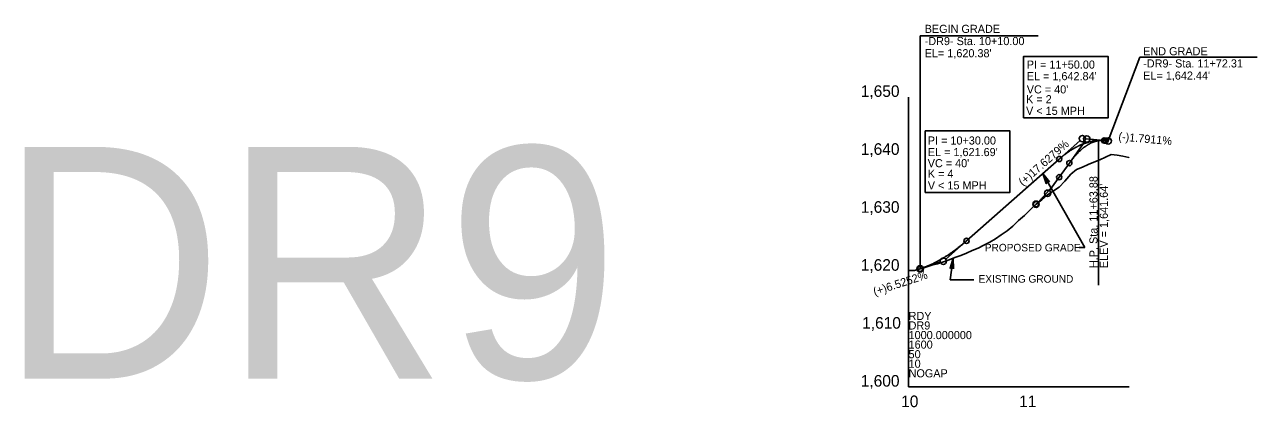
# Model space of a CAD drawing. Extents: x 498575 to 532350, y 405181 to 484585.
# Drawn here: x 526521 to 527585, y 462927 to 463257 of the extents above; entities that cross this region are included whole.
import ezdxf

# ---------------------------------------------------------------- set-up
doc = ezdxf.new("R2010")
doc.units = 0
for name, color, linetype in [('Exist Profile Cell', 7, 'Continuous'), ('Exist Vertical Profile Ground Line', 7, 'Continuous'), ('Exist Vertical Profile Horizontal Axis Label Major', 7, 'Continuous'), ('Exist Vertical Profile Vertical Axis Label', 7, 'Continuous'), ('Prop Grid Mask', 7, 'Continuous'), ('Prop PFL Text', 7, 'Continuous'), ('Prop Vertical Profile Curve Label', 7, 'Continuous'), ('Prop Vertical Profile Grade', 7, 'Continuous'), ('Prop Vertical Profile Grade Label', 7, 'Continuous'), ('Prop Vertical Profile Strip Grade', 7, 'Continuous'), ('Prop VPI Label', 7, 'Continuous'), ('Scratch_Level_5', 7, 'Continuous'), ('Scratch_Level_7', 7, 'Continuous')]:
    doc.layers.add(name, color=color, linetype=linetype)

msp = doc.modelspace()

# ---------------------------------------------------------------- linework, layer by layer
at = {"layer": 'Exist Profile Cell'}
for q in [(527283.8, 463194.6), (527474.1, 462944.6), (527283.8, 462944.6)]:
    msp.add_line((527283.8, 462944.6), q, dxfattribs=at)
at = {"layer": 'Exist Vertical Profile Ground Line'}
msp.add_lwpolyline([(527283.8, 463044.9), (527288.8, 463045), (527293.8, 463046.5), (527298.8, 463048), (527303.8, 463049.5), (527308.8, 463050.9), (527313.8, 463052.4), (527318.8, 463054.3), (527323.8, 463056.1), (527328.8, 463058), (527333.8, 463060), (527338.8, 463062.2), (527343.8, 463064.4), (527348.8, 463066.8), (527353.8, 463069.4), (527358.8, 463072.4), (527363.8, 463075.8), (527368.8, 463079.3), (527373.8, 463083.4), (527378.8, 463088.1), (527383.8, 463092.6), (527388.8, 463097.4), (527393.8, 463102.2), (527398.8, 463105.9), (527403.8, 463110.3), (527408.8, 463113.7), (527413.8, 463116.9), (527418.8, 463122.1), (527423.8, 463128), (527428.8, 463132.2), (527433.8, 463134.3), (527438.8, 463136.6), (527443.8, 463138.5), (527448.8, 463140.6), (527453.8, 463142.7), (527458.8, 463145.1), (527463.8, 463144.6), (527468.8, 463143.6), (527473.8, 463142.4), (527474.1, 463142.3)], dxfattribs=at)
at = {"layer": 'Prop Grid Mask'}
for points in [[(527383, 463176.7), (527456, 463176.7), (527456, 463229.8), (527383, 463229.8)], [(527298.2, 463112.4), (527371.2, 463112.4), (527371.2, 463165.5), (527298.2, 463165.5)]]:
    msp.add_lwpolyline(points, close=True, dxfattribs=at)
at = {"layer": 'Prop PFL Text'}
for p, q in [((527399.6, 463128.6), (527435.8, 463064.9)), ((527431.1, 463064.9), (527435.8, 463064.9)), ((527319.8, 463037), (527322.4, 463055.7)), ((527340.2, 463037), (527319.8, 463037))]:
    msp.add_line(p, q, dxfattribs=at)
for points in [[(527405.3, 463121.5), (527399.6, 463128.6), (527402.6, 463120), (527403.4, 463121.7)], [(527322.7, 463046.5), (527322.4, 463055.7), (527319.6, 463046.9), (527321.3, 463047.8)]]:
    msp.add_lwpolyline(points, close=True, dxfattribs=at)
at = {"layer": 'Prop Vertical Profile Curve Label'}
for centre in [(527453.8, 463157), (527413.8, 463141.2), (527333.8, 463070.6), (527293.8, 463046.5)]:
    msp.add_circle(centre, 2.25, dxfattribs=at)
at = {"layer": 'Prop Vertical Profile Grade'}
for p, q in [((527453.8, 463157), (527456.1, 463156.8)), ((527333.8, 463070.6), (527413.8, 463141.2))]:
    msp.add_line(p, q, dxfattribs=at)
for points in [[(527413.8, 463141.2), (527414.6, 463141.8), (527415.4, 463142.5), (527416.2, 463143.2), (527417, 463143.8), (527417.8, 463144.5), (527418.6, 463145.1), (527419.4, 463145.7), (527420.2, 463146.3), (527421, 463146.9), (527421.8, 463147.4), (527422.6, 463148), (527423.4, 463148.5), (527424.2, 463149), (527425, 463149.5), (527425.8, 463150), (527426.6, 463150.4), (527427.4, 463150.9), (527428.2, 463151.3), (527429, 463151.7), (527429.8, 463152.1), (527430.6, 463152.5), (527431.4, 463152.9), (527432.2, 463153.3), (527433, 463153.6), (527433.8, 463153.9), (527434.6, 463154.2), (527435.4, 463154.5), (527436.2, 463154.8), (527437, 463155.1), (527437.8, 463155.3), (527438.6, 463155.5), (527439.4, 463155.8), (527440.2, 463156), (527441, 463156.1), (527441.8, 463156.3), (527442.6, 463156.5), (527443.4, 463156.6), (527444.2, 463156.7), (527445, 463156.8), (527445.8, 463156.9), (527446.6, 463157), (527447.4, 463157.1), (527448.2, 463157.1), (527449, 463157.1), (527449.8, 463157.2), (527450.6, 463157.1), (527451.4, 463157.1), (527452.2, 463157.1), (527453, 463157.1), (527453.8, 463157)], [(527293.8, 463046.5), (527294.6, 463046.8), (527295.4, 463047), (527296.2, 463047.3), (527297, 463047.6), (527297.8, 463047.9), (527298.6, 463048.2), (527299.4, 463048.5), (527300.2, 463048.9), (527301, 463049.2), (527301.8, 463049.5), (527302.6, 463049.9), (527303.4, 463050.3), (527304.2, 463050.6), (527305, 463051), (527305.8, 463051.4), (527306.6, 463051.8), (527307.4, 463052.2), (527308.2, 463052.6), (527309, 463053), (527309.8, 463053.5), (527310.6, 463053.9), (527311.4, 463054.4), (527312.2, 463054.8), (527313, 463055.3), (527313.8, 463055.8), (527314.6, 463056.3), (527315.4, 463056.8), (527316.2, 463057.3), (527317, 463057.8), (527317.8, 463058.3), (527318.6, 463058.8), (527319.4, 463059.4), (527320.2, 463059.9), (527321, 463060.5), (527321.8, 463061.1), (527322.6, 463061.6), (527323.4, 463062.2), (527324.2, 463062.8), (527325, 463063.4), (527325.8, 463064), (527326.6, 463064.7), (527327.4, 463065.3), (527328.2, 463065.9), (527329, 463066.6), (527329.8, 463067.2), (527330.6, 463067.9), (527331.4, 463068.6), (527332.2, 463069.2), (527333, 463069.9), (527333.8, 463070.6)]]:
    msp.add_spline(points, degree=3, dxfattribs=at)
at = {"layer": 'Prop Vertical Profile Strip Grade'}
msp.add_line((527447.7, 463032.4), (527447.7, 463157.1), dxfattribs=at)
at = {"layer": 'Prop VPI Label'}
for p, q in [((527293.8, 463247.5), (527395.7, 463247.5)), ((527293.8, 463046.5), (527293.8, 463247.5)), ((527456, 463157), (527483.5, 463229)), ((527483.5, 463229), (527584.8, 463229)), ((527413.8, 463141.2), (527431.7, 463157)), ((527453.8, 463157), (527436.5, 463158.5)), ((527333.8, 463070.6), (527315.9, 463054.8)), ((527293.8, 463046.5), (527311.2, 463052.2))]:
    msp.add_line(p, q, dxfattribs=at)
for centre in [(527433.8, 463158.8), (527456.1, 463156.8), (527313.8, 463053), (527293.8, 463046.5)]:
    msp.add_circle(centre, 2.75, dxfattribs=at)
at = {"layer": 'Scratch_Level_5'}
for p, q in [((527422.6, 463137.7), (527435.9, 463156.2)), ((527452.6, 463157.1), (527440.3, 463158.2)), ((527452.6, 463157.1), (527456.1, 463156.8)), ((527413.8, 463125.5), (527422.6, 463137.7)), ((527413.8, 463125.5), (527405.4, 463113.9)), ((527393.8, 463102.2), (527401.8, 463109.8))]:
    msp.add_line(p, q, dxfattribs=at)
for centre, radius in [((527437.6, 463158.5), 2.75), ((527452.6, 463157.1), 2.25), ((527456.1, 463156.8), 2.75), ((527422.6, 463137.7), 2.25), ((527413.8, 463125.5), 2.25), ((527403.8, 463111.7), 2.75), ((527393.8, 463102.2), 2.75), ((527393.8, 463102.2), 2.25)]:
    msp.add_circle(centre, radius, dxfattribs=at)
for points in [[(527422.6, 463137.7), (527423.2, 463138.5), (527423.8, 463139.3), (527424.4, 463140.1), (527425, 463140.9), (527425.6, 463141.6), (527426.2, 463142.3), (527426.8, 463143.1), (527427.4, 463143.8), (527428, 463144.4), (527428.6, 463145.1), (527429.2, 463145.7), (527429.8, 463146.4), (527430.4, 463147), (527431, 463147.6), (527431.6, 463148.1), (527432.2, 463148.7), (527432.8, 463149.2), (527433.4, 463149.8), (527434, 463150.3), (527434.6, 463150.8), (527435.2, 463151.2), (527435.8, 463151.7), (527436.4, 463152.1), (527437, 463152.5), (527437.6, 463152.9), (527438.2, 463153.3), (527438.8, 463153.7), (527439.4, 463154), (527440, 463154.3), (527440.6, 463154.6), (527441.2, 463154.9), (527441.8, 463155.2), (527442.4, 463155.5), (527443, 463155.7), (527443.6, 463155.9), (527444.2, 463156.1), (527444.8, 463156.3), (527445.4, 463156.5), (527446, 463156.6), (527446.6, 463156.8), (527447.2, 463156.9), (527447.8, 463157), (527448.4, 463157), (527449, 463157.1), (527449.6, 463157.1), (527450.2, 463157.2), (527450.8, 463157.2), (527451.4, 463157.2), (527452, 463157.1), (527452.6, 463157.1)], [(527393.8, 463102.2), (527394.2, 463102.6), (527394.6, 463103), (527395, 463103.4), (527395.4, 463103.7), (527395.8, 463104.1), (527396.2, 463104.5), (527396.6, 463104.9), (527397, 463105.3), (527397.4, 463105.8), (527397.8, 463106.2), (527398.2, 463106.6), (527398.6, 463107), (527399, 463107.4), (527399.4, 463107.9), (527399.8, 463108.3), (527400.2, 463108.7), (527400.6, 463109.2), (527401, 463109.6), (527401.4, 463110), (527401.8, 463110.5), (527402.2, 463110.9), (527402.6, 463111.4), (527403, 463111.9), (527403.4, 463112.3), (527403.8, 463112.8), (527404.2, 463113.3), (527404.6, 463113.7), (527405, 463114.2), (527405.4, 463114.7), (527405.8, 463115.2), (527406.2, 463115.6), (527406.6, 463116.1), (527407, 463116.6), (527407.4, 463117.1), (527407.8, 463117.6), (527408.2, 463118.1), (527408.6, 463118.6), (527409, 463119.1), (527409.4, 463119.7), (527409.8, 463120.2), (527410.2, 463120.7), (527410.6, 463121.2), (527411, 463121.8), (527411.4, 463122.3), (527411.8, 463122.8), (527412.2, 463123.4), (527412.6, 463123.9), (527413, 463124.4), (527413.4, 463125), (527413.8, 463125.5)]]:
    msp.add_spline(points, degree=3, dxfattribs=at)

# ---------------------------------------------------------------- texts
at = {"layer": 'Exist Profile Cell'}
for s, p in [('RDY', (527283.8, 463002.3)), ('DR9', (527283.8, 462994.1)), ('1000.000000', (527283.8, 462985.8)), ('1600', (527283.8, 462977.6)), ('50', (527283.8, 462969.3)), ('10', (527283.8, 462961.1)), ('NOGAP', (527283.8, 462952.8))]:
    msp.add_text(s, height=7, dxfattribs=at).set_placement(p)
at = {"layer": 'Exist Vertical Profile Horizontal Axis Label Major'}
for s, p in [('10', (527277.4, 462927.1)), ('11', (527379.2, 462927.1))]:
    msp.add_text(s, height=10, dxfattribs=at).set_placement(p)
at = {"layer": 'Exist Vertical Profile Vertical Axis Label'}
for s, p in [('1,650', (527242.5, 463194.8)), ('1,640', (527242.5, 463144.8)), ('1,630', (527242.5, 463094.8)), ('1,620', (527242.5, 463044.8)), ('1,610', (527243.7, 462994.8)), ('1,600', (527242.5, 462944.8))]:
    msp.add_text(s, height=10, dxfattribs=at).set_placement(p)
at = {"layer": 'Prop PFL Text'}
for s, p in [('PROPOSED GRADE', (527349.6, 463061.5)), ('EXISTING GROUND', (527344.2, 463034.5))]:
    msp.add_text(s, height=6.516, dxfattribs=at).set_placement(p)
at = {"layer": 'Prop Vertical Profile Curve Label'}
for s, p in [("VC = 40'", (527385.8, 463197.8)), ('V < 15 MPH ', (527385.2, 463179.3)), ("VC = 40'", (527300.3, 463134.1)), ('V < 15 MPH ', (527300.4, 463115))]:
    msp.add_text(s, height=7, dxfattribs=at).set_placement(p)
at = {"layer": 'Prop Vertical Profile Grade Label'}
for s, rotation, p in [('(-)1.7911%', 354.8825, (527464.7, 463157.3)), ('(+)17.6279%', 41.3928, (527382.5, 463117.5)), ('(+)6.5252%', 18.0694, (527254.6, 463023.2))]:
    msp.add_text(s, height=7, rotation=rotation, dxfattribs=at).set_placement(p)
at = {"layer": 'Prop Vertical Profile Strip Grade'}
for s, p in [('H.P. Sta. 11+63.88', (527446.9, 463047.1)), ("ELEV = 1,641.64'", (527455.8, 463047.1))]:
    msp.add_text(s, height=7, rotation=90, dxfattribs=at).set_placement(p)
at = {"layer": 'Prop VPI Label'}
for s, p in [('BEGIN GRADE', (527297.7, 463250)), ('-DR9- Sta. 10+10.00', (527297.7, 463239.5)), ("EL= 1,620.38'", (527297.7, 463229)), ('END GRADE', (527486.3, 463230.7)), ('PI = 11+50.00', (527385.8, 463219.2)), ('-DR9- Sta. 11+72.31', (527486.3, 463220.2)), ("EL = 1,642.84'", (527385.8, 463209.2)), ("EL= 1,642.44'", (527486.3, 463209.7)), ('K = 2', (527385.2, 463189.3)), ('PI = 10+30.00', (527300.4, 463153.7)), ("EL = 1,621.69'", (527300.4, 463143.7)), ('K = 4', (527300.4, 463125))]:
    msp.add_text(s, height=7, dxfattribs=at).set_placement(p)
at = {"layer": 'Scratch_Level_7'}
msp.add_text('DR9', height=200, dxfattribs=at).set_placement((526498.9, 462951.7))

doc.saveas('drawing.dxf')
